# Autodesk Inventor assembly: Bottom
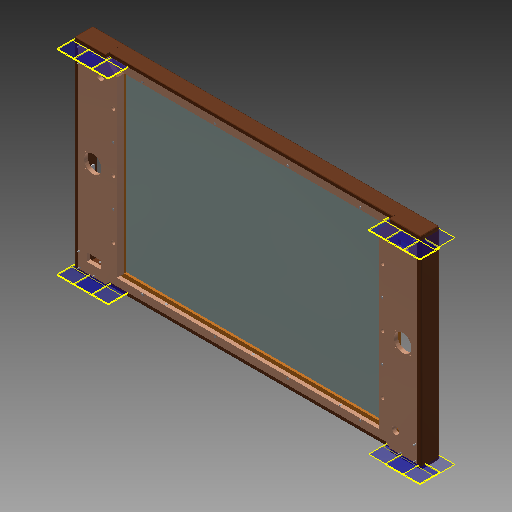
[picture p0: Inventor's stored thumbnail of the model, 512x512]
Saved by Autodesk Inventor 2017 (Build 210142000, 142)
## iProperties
Created: 2017-05
Part Number: Bottom
Document SubType Name: Assembly
Designer: Savy
Author: Savy
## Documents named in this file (20)
- D:\3D Printer Designs\John Ledden Designs\Infinity Mirror Table\SavanDrawings\Bottom.iam
- D:\3D Printer Designs\John Ledden Designs\Infinity Mirror Table\SavanDrawings\BottomInnerPanel_Long.ipt
- D:\3D Printer Designs\John Ledden Designs\Infinity Mirror Table\SavanDrawings\BottomInnerPanel_Short.ipt
- D:\3D Printer Designs\John Ledden Designs\Infinity Mirror Table\SavanDrawings\Mirror.ipt
- D:\3D Printer Designs\John Ledden Designs\Infinity Mirror Table\SavanDrawings\BottomInnerSpacer_Long.ipt
- D:\3D Printer Designs\John Ledden Designs\Infinity Mirror Table\SavanDrawings\BottomInnerSpacer_Short.ipt
- D:\3D Printer Designs\John Ledden Designs\Infinity Mirror Table\SavanDrawings\BottomBase_Short.ipt
- D:\3D Printer Designs\John Ledden Designs\Infinity Mirror Table\SavanDrawings\BottomSide_Long1.ipt
- D:\3D Printer Designs\John Ledden Designs\Infinity Mirror Table\SavanDrawings\BottomSide_Long2.ipt
- D:\3D Printer Designs\John Ledden Designs\Infinity Mirror Table\SavanDrawings\PSU_AC.ipt
- D:\3D Printer Designs\John Ledden Designs\Infinity Mirror Table\SavanDrawings\USBPorts.ipt
- D:\3D Printer Designs\John Ledden Designs\Infinity Mirror Table\SavanDrawings\ChannelAssembly.iam
- D:\3D Printer Designs\John Ledden Designs\Infinity Mirror Table\SavanDrawings\USBMount.ipt
- D:\3D Printer Designs\John Ledden Designs\Infinity Mirror Table\SavanDrawings\8_Screw_1inch.ipt
- D:\3D Printer Designs\John Ledden Designs\Infinity Mirror Table\SavanDrawings\8_Screw_1-25inch.ipt
- D:\3D Printer Designs\John Ledden Designs\Infinity Mirror Table\SavanDrawings\8_Screw_-5inch.ipt
- D:\3D Printer Designs\John Ledden Designs\Infinity Mirror Table\SavanDrawings\BottomSide_Short.ipt
- D:\3D Printer Designs\John Ledden Designs\Infinity Mirror Table\SavanDrawings\90DegBracket.ipt
- D:\3D Printer Designs\John Ledden Designs\Infinity Mirror Table\SavanDrawings\LBracket.ipt
- D:\3D Printer Designs\John Ledden Designs\Infinity Mirror Table\SavanDrawings\Magnet.ipt
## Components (140 placed, 108 different names)
1. BottomInnerPanel_Long_1177
2. BottomInnerPanel_Short_1178
3. BottomInnerPanel_Long_1179
4. BottomInnerPanel_Short_1180
5. Mirror_1181
6. BottomInnerSpacer_Long_1182
7. BottomInnerSpacer_Short_1183
8. BottomInnerSpacer_Long_1184
9. BottomInnerSpacer_Short_1185
10. BottomBase_Short_1186 — Insert:7, Insert:8, Insert:9, Insert:10, Insert:11, Insert:12
11. BottomBase_Short_1187 — Insert:1, Insert:2, Insert:3, Insert:4, Insert:5, Insert:6
12. BottomSide_Long1_1188 — Flush:1, Mate:1, Mate:2, Mate:3, Mate:5
13. BottomSide_Long1_1189 — Mate:19, Mate:20, Mate:21, Mate:22, Mate:23
14. BottomSide_Long1_1190 — Mate:13, Mate:14, Mate:15, Mate:16
15. BottomSide_Long1_1191 — Mate:7, Mate:8, Mate:9, Mate:10
16. BottomSide_Long2_1192
17. BottomSide_Long2_1193
18. PSU_AC_1194
19. PSU_AC_1195
20. USBPorts_1196
21. USBPorts_1197
22. ChannelAssembly_1198 [sub-assembly]
23. USBMount_1199
24. USBMount_1200
25. 8_Screw_1inch_1201
26. 8_Screw_1inch_1202
27. 8_Screw_1inch_1203
28. 8_Screw_1inch_1204
29. 8_Screw_1inch_1205 — Insert:2
30. 8_Screw_1inch_1206 — Insert:1
31. 8_Screw_1-25inch_1207
32. 8_Screw_1-25inch_1208
33. 8_Screw_1-25inch_1209
34. 8_Screw_1-25inch_1210
35. 8_Screw_1-25inch_1211
36. 8_Screw_1-25inch_1212
37. 8_Screw_1-25inch_1213
38. 8_Screw_1-25inch_1214
39. 8_Screw_1-25inch_1215
40. 8_Screw_1-25inch_1216
41. 8_Screw_1-25inch_1217
42. 8_Screw_1-25inch_1218
43. 8_Screw_1-25inch_1219
44. 8_Screw_1-25inch_1220
45. 8_Screw_1-25inch_1221
46. 8_Screw_1-25inch_1222
47. 8_Screw_1-25inch_1223
48. 8_Screw_1-25inch_1224
49. 8_Screw_1-25inch_1225
50. 8_Screw_1-25inch_1226
51. 8_Screw_1inch_1227
52. 8_Screw_1inch_1228
53. 8_Screw_1inch_1229
54. 8_Screw_1inch_1230
55. 8_Screw_-5inch_1231
56. 8_Screw_-5inch_1232
57. 8_Screw_-5inch_1233
58. 8_Screw_-5inch_1234
59. 8_Screw_-5inch_1235
60. 8_Screw_-5inch_1236
61. 8_Screw_-5inch_1237
62. 8_Screw_-5inch_1238
63. BottomSide_Short_1247
64. BottomSide_Short_1248
65. 90DegBracket_1249
66. 90DegBracket_1250
67. 90DegBracket_1251
68. 90DegBracket_1252
69. 90DegBracket_1253
70. 90DegBracket_1254
71. 90DegBracket_1255
72. 90DegBracket_1256
73. 90DegBracket_1257
74. 90DegBracket_1258
75. 8_Screw_-5inch_1259
76. 8_Screw_-5inch_1260
77. 8_Screw_-5inch_1261
78. 8_Screw_-5inch_1262
79. 8_Screw_-5inch_1263
80. 8_Screw_-5inch_1264
81. 8_Screw_-5inch_1265
82. 8_Screw_-5inch_1266
83. 8_Screw_-5inch_1267
84. 8_Screw_-5inch_1268
85. 8_Screw_-5inch_1269
86. 8_Screw_-5inch_1270
87. 8_Screw_-5inch_1271
88. 8_Screw_-5inch_1272
89. 8_Screw_-5inch_1273
90. 8_Screw_-5inch_1274
91. 8_Screw_-5inch_1275
92. 8_Screw_-5inch_1276
93. 8_Screw_-5inch_1277
94. 8_Screw_-5inch_1278
95. LBracket_1279
96. LBracket_1280
97. LBracket_1281
98. LBracket_1282
99. 8_Screw_-5inch_1283
100. 8_Screw_-5inch_1284
101. 8_Screw_-5inch_1285
102. 8_Screw_-5inch_1286
103. 8_Screw_-5inch_1287
104. 8_Screw_-5inch_1288
105. 8_Screw_-5inch_1289
106. 8_Screw_-5inch_1290
107. Magnet:1 — Flush:1
108. Magnet:2 — Mate:1
109. Magnet:3 — Mate:4
110. Magnet:7 — Mate:3, Mate:4
111. Magnet:8 — Mate:5
112. Magnet:9 — Mate:2
113. Magnet:10 — Mate:8
114. Magnet:11 — Mate:7
115. Magnet:12
116. Magnet:13 — Mate:9
117. Magnet:14 — Mate:11
118. Magnet:15 — Mate:10, Mate:11
119. Magnet:16 — Mate:14
120. Magnet:17 — Mate:13
121. Magnet:18
122. Magnet:19 — Mate:15
123. Magnet:20 — Mate:17
124. Magnet:21 — Mate:16, Mate:17
125. Magnet:22 — Mate:20
126. Magnet:23 — Mate:19
127. Magnet:24
128. Magnet:25 — Mate:21
129. Magnet:26 — Mate:23
130. Magnet:27 — Mate:22
131. 8_Screw_1inch:11 — Insert:3
132. 8_Screw_1inch:12 — Insert:4
133. 8_Screw_1inch:13 — Insert:5
134. 8_Screw_1inch:14 — Insert:6
135. 8_Screw_1inch:15 — Insert:7
136. 8_Screw_1inch:16 — Insert:8
137. 8_Screw_1inch:17 — Insert:9
138. 8_Screw_1inch:18 — Insert:10
139. 8_Screw_1inch:19 — Insert:11
140. 8_Screw_1inch:20 — Insert:12
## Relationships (33: Mate 20, Insert 12, Flush 1)
- Flush:1: BottomSide_Long1_1188 ↔ Magnet:1
- Mate:1: BottomSide_Long1_1188 ↔ Magnet:2
- Mate:2: BottomSide_Long1_1188 ↔ Magnet:9
- Mate:3: BottomSide_Long1_1188 ↔ Magnet:7
- Mate:4: Magnet:3 ↔ Magnet:7
- Mate:5: BottomSide_Long1_1188 ↔ Magnet:8
- Mate:7: BottomSide_Long1_1191 ↔ Magnet:11
- Mate:8: BottomSide_Long1_1191 ↔ Magnet:10
- Mate:9: BottomSide_Long1_1191 ↔ Magnet:13
- Mate:10: BottomSide_Long1_1191 ↔ Magnet:15
- Mate:11: Magnet:14 ↔ Magnet:15
- Mate:13: BottomSide_Long1_1190 ↔ Magnet:17
- Mate:14: BottomSide_Long1_1190 ↔ Magnet:16
- Mate:15: BottomSide_Long1_1190 ↔ Magnet:19
- Mate:16: BottomSide_Long1_1190 ↔ Magnet:21
- Mate:17: Magnet:20 ↔ Magnet:21
- Mate:19: BottomSide_Long1_1189 ↔ Magnet:23
- Mate:20: BottomSide_Long1_1189 ↔ Magnet:22
- Mate:21: BottomSide_Long1_1189 ↔ Magnet:25
- Mate:22: BottomSide_Long1_1189 ↔ Magnet:27
- Mate:23: BottomSide_Long1_1189 ↔ Magnet:26
- Insert:1: BottomBase_Short_1187 ↔ 8_Screw_1inch_1206
- Insert:2: BottomBase_Short_1187 ↔ 8_Screw_1inch_1205
- Insert:3: BottomBase_Short_1187 ↔ 8_Screw_1inch:11
- Insert:4: BottomBase_Short_1187 ↔ 8_Screw_1inch:12
- Insert:5: BottomBase_Short_1187 ↔ 8_Screw_1inch:13
- Insert:6: BottomBase_Short_1187 ↔ 8_Screw_1inch:14
- Insert:7: BottomBase_Short_1186 ↔ 8_Screw_1inch:15
- Insert:8: BottomBase_Short_1186 ↔ 8_Screw_1inch:16
- Insert:9: BottomBase_Short_1186 ↔ 8_Screw_1inch:17
- Insert:10: BottomBase_Short_1186 ↔ 8_Screw_1inch:18
- Insert:11: BottomBase_Short_1186 ↔ 8_Screw_1inch:19
- Insert:12: BottomBase_Short_1186 ↔ 8_Screw_1inch:20
## Named parameters: d6_d4 = 0, d12_d4 = 0, d18_d4 = 0
